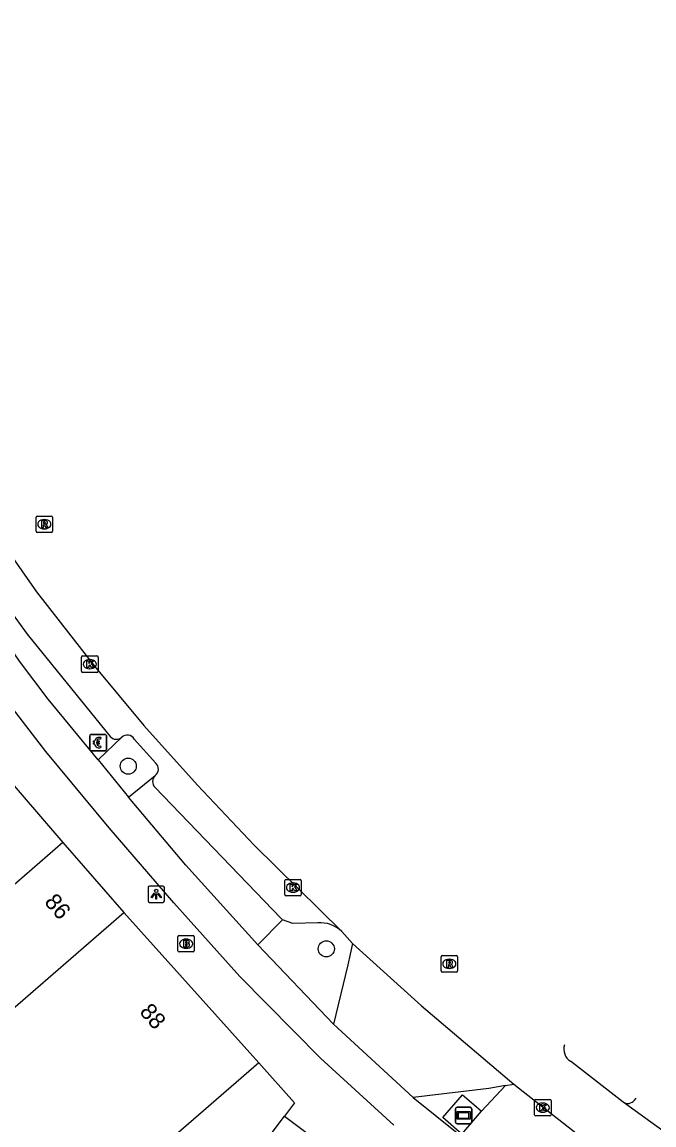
# Model space of a CAD drawing. Extents: x 161845 to 162341, y 381620 to 382158.
# Drawn here: x 162112.3 to 162150.7, y 381850 to 381917 of the extents above; entities that cross this region are included whole.
import ezdxf

# ---------------------------------------------------------------- set-up
doc = ezdxf.new("R2010")
doc.units = 0
for name, color, linetype in [('IMGEO_Berm_groen', 7, 'Continuous'), ('IMGEO_Betaalautomaat', 7, 'Continuous'), ('IMGEO_Boom', 7, 'Continuous'), ('IMGEO_Brandkraan', 7, 'Continuous'), ('IMGEO_Groenvoorziening', 7, 'Continuous'), ('IMGEO_Kolk', 7, 'Continuous'), ('IMGEO_Lichtpunt', 7, 'Continuous'), ('IMGEO_Pand', 7, 'Continuous'), ('IMGEO_Pand_nummerreeks', 7, 'Continuous'), ('IMGEO_Parkeervlak_open', 7, 'Continuous'), ('IMGEO_Reclamebord', 7, 'Continuous'), ('IMGEO_Rijbaan_lokaal_gesloten', 7, 'Continuous'), ('IMGEO_Rijbaan_lokaal_open', 7, 'Continuous'), ('IMGEO_Rioolput', 7, 'Continuous'), ('IMGEO_Voetpad_gesloten', 7, 'Continuous'), ('IMGEO_Voetpad_open', 7, 'Continuous')]:
    doc.layers.add(name, color=color, linetype=linetype)

msp = doc.modelspace()

# ---------------------------------------------------------------- linework, layer by layer
at = {"layer": 'IMGEO_Berm_groen'}
for points in [[(162140.224, 381850.815), (162141.664, 381852.376)], [(162139.024, 381849.428), (162140.224, 381850.815)]]:
    msp.add_lwpolyline(points, dxfattribs=at)
at = {"layer": 'IMGEO_Betaalautomaat'}
for p, q in [((162116.435, 381872.795), (162116.435, 381873.636)), ((162116.435, 381873.636), (162116.435, 381872.795)), ((162116.51, 381873.719), (162117.351, 381873.719)), ((162117.351, 381873.719), (162116.51, 381873.719)), ((162117.434, 381873.645), (162117.434, 381872.804)), ((162117.434, 381872.804), (162117.434, 381873.645)), ((162116.718, 381873.183), (162116.718, 381873.251)), ((162116.839, 381873.251), (162116.839, 381873.183)), ((162117.097, 381873.524), (162117.08, 381873.424)), ((162117.084, 381873.018), (162117.106, 381872.931)), ((162117.36, 381872.72), (162116.519, 381872.72)), ((162116.519, 381872.72), (162117.36, 381872.72))]:
    msp.add_line(p, q, dxfattribs=at)
for points in [[(162116.718, 381873.251), (162116.649, 381873.251), (162116.649, 381873.32), (162116.728, 381873.32)], [(162116.723, 381873.114), (162116.649, 381873.114), (162116.649, 381873.183), (162116.718, 381873.183)], [(162116.85, 381873.32), (162116.997, 381873.32), (162116.997, 381873.251), (162116.839, 381873.251)], [(162116.839, 381873.183), (162116.997, 381873.183), (162116.997, 381873.114), (162116.853, 381873.114)]]:
    msp.add_lwpolyline(points, dxfattribs=at)
for centre, radius, start, end in [((162116.513, 381873.642), 0.0779, 92.4484, 184.28452), ((162116.513, 381873.642), 0.0779, 92.4484, 184.28452), ((162117.357, 381873.642), 0.0779, 2.4484, 94.28452), ((162117.357, 381873.642), 0.0779, 2.4484, 94.28452), ((162116.984, 381873.169), 0.267, 191.80956, 297.03891), ((162117.011, 381873.244), 0.293, 73.01398, 165.01395), ((162117.017, 381873.257), 0.179, 69.32359, 159.56827), ((162117.017, 381873.184), 0.179, 202.76249, 291.86925), ((162116.513, 381872.798), 0.0779, 182.4484, 274.28452), ((162116.513, 381872.798), 0.0779, 182.4484, 274.28452), ((162117.357, 381872.798), 0.0779, 272.4484, 4.28452), ((162117.357, 381872.798), 0.0779, 272.4484, 4.28452)]:
    msp.add_arc(centre, radius, start, end, dxfattribs=at)
at = {"layer": 'IMGEO_Boom'}
for centre in [(162118.764, 381871.787), (162130.79, 381860.685)]:
    msp.add_circle(centre, 0.489, dxfattribs=at)
at = {"layer": 'IMGEO_Brandkraan'}
for p, q in [((162121.775, 381860.573), (162121.775, 381861.425)), ((162121.85, 381861.499), (162122.702, 381861.499)), ((162122.263, 381861.279), (162122.288, 381861.279)), ((162122.776, 381861.425), (162122.776, 381860.573)), ((162122.702, 381860.499), (162121.85, 381860.499)), ((162122.286, 381860.719), (162122.261, 381860.719))]:
    msp.add_line(p, q, dxfattribs=at)
for points in [[(162121.775, 381860.573), (162121.775, 381861.425)], [(162121.85, 381861.499), (162122.702, 381861.499)], [(162122.123, 381861.199), (162122.123, 381860.799), (162122.336, 381860.799)], [(162122.354, 381861.199), (162122.123, 381861.199)], [(162122.302, 381861.118), (162122.248, 381861.118), (162122.248, 381861.042)], [(162122.248, 381861.042), (162122.301, 381861.042)], [(162122.31, 381860.966), (162122.248, 381860.966), (162122.248, 381860.885)], [(162122.248, 381860.885), (162122.31, 381860.885)], [(162122.776, 381861.425), (162122.776, 381860.573)], [(162122.702, 381860.499), (162121.85, 381860.499)]]:
    msp.add_lwpolyline(points, dxfattribs=at)
for centre, radius, start, end in [((162121.852, 381861.423), 0.0765, 91.55205, 178.44795), ((162121.852, 381861.423), 0.0765, 91.55205, 178.44795), ((162122.303, 381861.08), 0.0379, 267.82845, 90.93552), ((162122.311, 381860.925), 0.0404, 269.87594, 90.50774), ((162122.358, 381861.054), 0.145, 59.4692, 91.53667), ((162122.383, 381861.101), 0.0922, 285.51372, 58.15012), ((162122.388, 381860.909), 0.105, 301.31148, 78.98903), ((162122.7, 381861.423), 0.0765, 1.55205, 88.44795), ((162122.7, 381861.423), 0.0765, 1.55205, 88.44795), ((162121.852, 381860.575), 0.0765, 181.55205, 268.44795), ((162121.852, 381860.575), 0.0765, 181.55205, 268.44795), ((162122.342, 381861.05), 0.251, 268.66757, 293.53466), ((162122.7, 381860.575), 0.0765, 271.55205, 358.44795), ((162122.7, 381860.575), 0.0765, 271.55205, 358.44795)]:
    msp.add_arc(centre, radius, start, end, dxfattribs=at)
for centre, major_axis, ratio, start_param, end_param in [((162122.262, 381860.999), (-0.387, 0.002), 0.722429, 4.712389, 7.853982), ((162122.287, 381860.999), (-0.39, 0.002), 0.717154, 1.570796, 4.712389)]:
    msp.add_ellipse(centre, major_axis=major_axis, ratio=ratio, start_param=start_param, end_param=end_param, dxfattribs=at)
at = {"layer": 'IMGEO_Groenvoorziening'}
msp.add_lwpolyline([(162139.024, 381849.428), (162137.867, 381850.429), (162139.067, 381851.816), (162139.757, 381851.219), (162140.224, 381850.815)], dxfattribs=at)
at = {"layer": 'IMGEO_Kolk'}
for p, q in [((162115.929, 381877.559), (162115.929, 381878.411)), ((162116.004, 381878.485), (162116.856, 381878.485)), ((162116.93, 381878.411), (162116.93, 381877.559)), ((162116.44, 381877.705), (162116.415, 381877.705)), ((162116.417, 381878.265), (162116.442, 381878.265)), ((162116.856, 381877.485), (162116.004, 381877.485)), ((162128.345, 381864.908), (162129.197, 381864.908)), ((162128.27, 381863.982), (162128.27, 381864.834)), ((162128.758, 381864.688), (162128.783, 381864.688)), ((162129.271, 381864.834), (162129.271, 381863.982)), ((162129.197, 381863.908), (162128.345, 381863.908)), ((162128.781, 381864.128), (162128.756, 381864.128)), ((162143.513, 381851.534), (162144.365, 381851.534)), ((162143.438, 381850.608), (162143.438, 381851.46)), ((162143.926, 381851.314), (162143.951, 381851.314)), ((162144.439, 381851.46), (162144.439, 381850.608)), ((162144.365, 381850.534), (162143.513, 381850.534)), ((162143.949, 381850.754), (162143.924, 381850.754))]:
    msp.add_line(p, q, dxfattribs=at)
for points in [[(162115.929, 381877.559), (162115.929, 381878.411)], [(162116.004, 381878.485), (162116.856, 381878.485)], [(162116.93, 381878.411), (162116.93, 381877.559)], [(162116.25, 381878.185), (162116.373, 381878.185), (162116.373, 381878.034), (162116.503, 381878.185), (162116.667, 381878.185), (162116.521, 381878.034), (162116.674, 381877.785), (162116.522, 381877.785), (162116.437, 381877.949), (162116.373, 381877.882), (162116.373, 381877.785), (162116.25, 381877.785), (162116.25, 381878.185)], [(162116.856, 381877.485), (162116.004, 381877.485)], [(162128.345, 381864.908), (162129.197, 381864.908)], [(162128.27, 381863.982), (162128.27, 381864.834)], [(162128.591, 381864.608), (162128.714, 381864.608), (162128.714, 381864.457), (162128.844, 381864.608), (162129.008, 381864.608), (162128.862, 381864.457), (162129.015, 381864.208), (162128.863, 381864.208), (162128.778, 381864.372), (162128.714, 381864.305), (162128.714, 381864.208), (162128.591, 381864.208), (162128.591, 381864.608)], [(162129.271, 381864.834), (162129.271, 381863.982)], [(162129.197, 381863.908), (162128.345, 381863.908)], [(162143.513, 381851.534), (162144.365, 381851.534)], [(162143.438, 381850.608), (162143.438, 381851.46)], [(162143.759, 381851.234), (162143.882, 381851.234), (162143.882, 381851.083), (162144.012, 381851.234), (162144.176, 381851.234), (162144.03, 381851.083), (162144.183, 381850.834), (162144.031, 381850.834), (162143.946, 381850.998), (162143.882, 381850.931), (162143.882, 381850.834), (162143.759, 381850.834), (162143.759, 381851.234)], [(162144.439, 381851.46), (162144.439, 381850.608)], [(162144.365, 381850.534), (162143.513, 381850.534)]]:
    msp.add_lwpolyline(points, dxfattribs=at)
for centre, start, end in [((162116.006, 381878.409), 91.55205, 178.44795), ((162116.006, 381878.409), 91.55205, 178.44795), ((162116.854, 381878.409), 1.55205, 88.44795), ((162116.854, 381878.409), 1.55205, 88.44795), ((162116.006, 381877.561), 181.55205, 268.44795), ((162116.006, 381877.561), 181.55205, 268.44795), ((162116.854, 381877.561), 271.55205, 358.44795), ((162116.854, 381877.561), 271.55205, 358.44795), ((162128.347, 381864.832), 91.55205, 178.44795), ((162128.347, 381864.832), 91.55205, 178.44795), ((162129.195, 381864.832), 1.55205, 88.44795), ((162129.195, 381864.832), 1.55205, 88.44795), ((162128.347, 381863.984), 181.55205, 268.44795), ((162128.347, 381863.984), 181.55205, 268.44795), ((162129.195, 381863.984), 271.55205, 358.44795), ((162129.195, 381863.984), 271.55205, 358.44795), ((162143.515, 381851.458), 91.55205, 178.44795), ((162143.515, 381851.458), 91.55205, 178.44795), ((162144.363, 381851.458), 1.55205, 88.44795), ((162144.363, 381851.458), 1.55205, 88.44795), ((162143.515, 381850.61), 181.55205, 268.44795), ((162143.515, 381850.61), 181.55205, 268.44795), ((162144.363, 381850.61), 271.55205, 358.44795), ((162144.363, 381850.61), 271.55205, 358.44795)]:
    msp.add_arc(centre, 0.0765, start, end, dxfattribs=at)
for centre, major_axis, ratio, start_param, end_param in [((162116.416, 381877.985), (-0.387, 0.002), 0.722429, 4.712389, 7.853982), ((162116.441, 381877.985), (-0.39, 0.002), 0.717154, 1.570796, 4.712389), ((162128.757, 381864.408), (-0.387, 0.002), 0.722429, 4.712389, 7.853982), ((162128.782, 381864.408), (-0.39, 0.002), 0.717154, 1.570796, 4.712389), ((162143.925, 381851.034), (-0.387, 0.002), 0.722429, 4.712389, 7.853982), ((162143.95, 381851.034), (-0.39, 0.002), 0.717154, 1.570796, 4.712389)]:
    msp.add_ellipse(centre, major_axis=major_axis, ratio=ratio, start_param=start_param, end_param=end_param, dxfattribs=at)
at = {"layer": 'IMGEO_Lichtpunt'}
for p, q in [((162119.965, 381864.407), (162119.965, 381863.6)), ((162119.965, 381864.407), (162119.965, 381863.6)), ((162120.867, 381864.502), (162120.059, 381864.502)), ((162120.867, 381864.502), (162120.059, 381864.502)), ((162120.961, 381863.6), (162120.961, 381864.407)), ((162120.961, 381863.6), (162120.961, 381864.407)), ((162120.059, 381863.506), (162120.867, 381863.506)), ((162120.059, 381863.506), (162120.867, 381863.506))]:
    msp.add_line(p, q, dxfattribs=at)
for points in [[(162120.339, 381864.071), (162120.378, 381864.043), (162120.19, 381863.781), (162120.152, 381863.808), (162120.339, 381864.071)], [(162120.441, 381864.023), (162120.488, 381864.023), (162120.488, 381863.701), (162120.441, 381863.701), (162120.441, 381864.023)], [(162120.551, 381864.043), (162120.589, 381864.07), (162120.776, 381863.808), (162120.737, 381863.78), (162120.551, 381864.043)]]:
    msp.add_lwpolyline(points, dxfattribs=at)
msp.add_circle((162120.464, 381864.205), 0.0994, dxfattribs=at)
for centre, start, end in [((162120.059, 381864.407), 90, 180), ((162120.059, 381864.407), 90, 180), ((162120.867, 381864.407), 0, 90), ((162120.867, 381864.407), 0, 90), ((162120.059, 381863.6), 180, 270), ((162120.059, 381863.6), 180, 270), ((162120.867, 381863.6), 270, 0), ((162120.867, 381863.6), 270, 360)]:
    msp.add_arc(centre, 0.0946, start, end, dxfattribs=at)
at = {"layer": 'IMGEO_Pand'}
for points in [[(162110.94, 381871.605), (162114.795, 381867.156)], [(162114.795, 381867.156), (162108.715, 381861.887), (162107.979, 381862.737), (162100.673, 381856.414), (162099.355, 381857.936), (162089.659, 381849.709)], [(162114.795, 381867.156), (162118.49, 381862.892)], [(162098.619, 381845.654), (162109.895, 381855.443), (162118.49, 381862.892)], [(162118.49, 381862.892), (162126.698, 381853.761)], [(162126.698, 381853.761), (162120.737, 381848.595), (162121.682, 381847.505), (162114.735, 381838.122)]]:
    msp.add_lwpolyline(points, dxfattribs=at)
at = {"layer": 'IMGEO_Parkeervlak_open'}
for points in [[(162120.441, 381871.976), (162119.124, 381873.432)], [(162130.268, 381862.266), (162128.757, 381862.224), (162128.126, 381862.446)]]:
    msp.add_lwpolyline(points, dxfattribs=at)
for centre, radius, start, end in [((162118.701, 381873.196), 0.484, 29.19225, 132.47826), ((162120.086, 381871.614), 0.506, 308.12397, 45.54977), ((162130.415, 381860.376), 1.896, 46.2334, 94.43904)]:
    msp.add_arc(centre, radius, start, end, dxfattribs=at)
at = {"layer": 'IMGEO_Reclamebord'}
for p, q in [((162138.632, 381850.161), (162138.632, 381850.961)), ((162138.632, 381850.961), (162138.632, 381850.161)), ((162138.732, 381851.061), (162139.522, 381851.061)), ((162139.522, 381851.061), (162138.732, 381851.061)), ((162139.622, 381850.961), (162139.622, 381850.161)), ((162139.622, 381850.161), (162139.622, 381850.961)), ((162139.522, 381850.061), (162138.732, 381850.061)), ((162138.732, 381850.061), (162139.522, 381850.061))]:
    msp.add_line(p, q, dxfattribs=at)
for points in [[(162138.733, 381850.793), (162139.521, 381850.793), (162139.521, 381850.329), (162138.733, 381850.329), (162138.733, 381850.793)], [(162138.798, 381850.728), (162138.798, 381850.394), (162139.456, 381850.394), (162139.456, 381850.728), (162138.798, 381850.728)]]:
    msp.add_lwpolyline(points, dxfattribs=at)
for centre, start, end in [((162138.732, 381850.961), 90, 180), ((162138.732, 381850.961), 90, 180), ((162139.522, 381850.961), 0, 90), ((162139.522, 381850.961), 360, 90), ((162138.732, 381850.161), 180, 270), ((162138.732, 381850.161), 180, 270), ((162139.522, 381850.161), 270, 0), ((162139.522, 381850.161), 270, 0)]:
    msp.add_arc(centre, 0.1, start, end, dxfattribs=at)
at = {"layer": 'IMGEO_Rijbaan_lokaal_gesloten'}
for points in [[(162092.687, 381916.789), (162101.169, 381901.585), (162104.943, 381895.096), (162107.401, 381891.02), (162110.364, 381886.414), (162113.19, 381882.377), (162116.706, 381877.858), (162119.709, 381874.255), (162122.966, 381870.633), (162126.414, 381866.991), (162131.726, 381861.745)], [(162131.726, 381861.745), (162132.386, 381861.014)], [(162148.821, 381851.365), (162145.621, 381853.854)], [(162142.172, 381852.464), (162147.466, 381848.311)], [(162152.909, 381848.404), (162148.821, 381851.365)]]:
    msp.add_lwpolyline(points, dxfattribs=at)
msp.add_arc((162146.054, 381854.573), 0.839, 161.29895, 238.94639, dxfattribs=at)
at = {"layer": 'IMGEO_Rijbaan_lokaal_open'}
for points in [[(162132.386, 381861.014), (162132.098, 381859.71), (162131.221, 381856.117)], [(162132.386, 381861.014), (162136.567, 381857.218), (162142.172, 381852.464)], [(162131.221, 381856.117), (162136.067, 381851.659)], [(162141.664, 381852.376), (162140.664, 381852.202), (162136.067, 381851.659)], [(162141.664, 381852.376), (162142.172, 381852.464)], [(162123.069, 381843.607), (162128.26, 381850.52)], [(162128.26, 381850.52), (162131.013, 381848.456)]]:
    msp.add_lwpolyline(points, dxfattribs=at)
at = {"layer": 'IMGEO_Rioolput'}
for p, q in [((162113.164, 381886.063), (162113.164, 381886.915)), ((162113.239, 381886.989), (162114.091, 381886.989)), ((162113.652, 381886.769), (162113.677, 381886.769)), ((162114.165, 381886.915), (162114.165, 381886.063)), ((162114.091, 381885.989), (162113.239, 381885.989)), ((162113.675, 381886.209), (162113.65, 381886.209)), ((162137.761, 381859.35), (162137.761, 381860.202)), ((162137.836, 381860.276), (162138.688, 381860.276)), ((162138.762, 381860.202), (162138.762, 381859.35)), ((162138.249, 381860.056), (162138.274, 381860.056)), ((162138.688, 381859.276), (162137.836, 381859.276)), ((162138.272, 381859.496), (162138.247, 381859.496))]:
    msp.add_line(p, q, dxfattribs=at)
for points in [[(162113.164, 381886.063), (162113.164, 381886.915)], [(162113.239, 381886.989), (162114.091, 381886.989)], [(162113.753, 381886.687), (162113.501, 381886.689), (162113.501, 381886.289)], [(162113.501, 381886.289), (162113.625, 381886.289), (162113.625, 381886.451), (162113.636, 381886.451)], [(162113.679, 381886.608), (162113.625, 381886.608), (162113.625, 381886.527)], [(162113.625, 381886.527), (162113.677, 381886.527)], [(162113.683, 381886.422), (162113.754, 381886.289), (162113.894, 381886.289), (162113.829, 381886.415)], [(162114.165, 381886.915), (162114.165, 381886.063)], [(162114.091, 381885.989), (162113.239, 381885.989)], [(162137.761, 381859.35), (162137.761, 381860.202)], [(162137.836, 381860.276), (162138.688, 381860.276)], [(162138.762, 381860.202), (162138.762, 381859.35)], [(162138.35, 381859.974), (162138.098, 381859.976), (162138.098, 381859.576)], [(162138.098, 381859.576), (162138.222, 381859.576), (162138.222, 381859.738), (162138.233, 381859.738)], [(162138.276, 381859.895), (162138.222, 381859.895), (162138.222, 381859.814)], [(162138.222, 381859.814), (162138.274, 381859.814)], [(162138.28, 381859.709), (162138.351, 381859.576), (162138.491, 381859.576), (162138.426, 381859.702)], [(162138.688, 381859.276), (162137.836, 381859.276)]]:
    msp.add_lwpolyline(points, dxfattribs=at)
for centre, radius, start, end in [((162113.241, 381886.913), 0.0765, 91.55205, 178.44795), ((162113.241, 381886.913), 0.0765, 91.55205, 178.44795), ((162113.635, 381886.398), 0.0533, 26.02933, 88.69889), ((162113.661, 381886.716), 0.19, 274.7715, 282.96867), ((162113.685, 381886.512), 0.0964, 77.00612, 93.18647), ((162113.699, 381886.569), 0.0378, 276.66336, 79.67722), ((162113.752, 381886.577), 0.109, 350.36119, 89.41601), ((162113.75, 381886.577), 0.112, 277.58423, 350.98172), ((162113.734, 381886.362), 0.108, 29.51342, 73.79051), ((162114.089, 381886.913), 0.0765, 1.55205, 88.44795), ((162114.089, 381886.913), 0.0765, 1.55205, 88.44795), ((162113.241, 381886.065), 0.0765, 181.55205, 268.44795), ((162113.241, 381886.065), 0.0765, 181.55205, 268.44795), ((162114.089, 381886.065), 0.0765, 271.55205, 358.44795), ((162114.089, 381886.065), 0.0765, 271.55205, 358.44795), ((162137.838, 381860.2), 0.0765, 91.55205, 178.44795), ((162137.838, 381860.2), 0.0765, 91.55205, 178.44795), ((162138.686, 381860.2), 0.0765, 1.55205, 88.44795), ((162138.686, 381860.2), 0.0765, 1.55205, 88.44795), ((162138.232, 381859.685), 0.0533, 26.02933, 88.69889), ((162138.258, 381860.003), 0.19, 274.7715, 282.96867), ((162138.282, 381859.799), 0.0964, 77.00612, 93.18647), ((162138.296, 381859.856), 0.0378, 276.66336, 79.67722), ((162138.349, 381859.864), 0.109, 350.36119, 89.41601), ((162138.347, 381859.864), 0.112, 277.58423, 350.98172), ((162138.331, 381859.649), 0.108, 29.51342, 73.79051), ((162137.838, 381859.352), 0.0765, 181.55205, 268.44795), ((162137.838, 381859.352), 0.0765, 181.55205, 268.44795), ((162138.686, 381859.352), 0.0765, 271.55205, 358.44795), ((162138.686, 381859.352), 0.0765, 271.55205, 358.44795)]:
    msp.add_arc(centre, radius, start, end, dxfattribs=at)
for centre, major_axis, ratio, start_param, end_param in [((162113.651, 381886.489), (-0.387, 0.002), 0.722429, 4.712389, 7.853982), ((162113.676, 381886.489), (-0.39, 0.002), 0.717154, 1.570796, 4.712389), ((162138.248, 381859.776), (-0.387, 0.002), 0.722429, 4.712389, 7.853982), ((162138.273, 381859.776), (-0.39, 0.002), 0.717154, 1.570796, 4.712389)]:
    msp.add_ellipse(centre, major_axis=major_axis, ratio=ratio, start_param=start_param, end_param=end_param, dxfattribs=at)
at = {"layer": 'IMGEO_Voetpad_gesloten'}
for points in [[(162134.882, 381849.978), (162130.429, 381854.037), (162125.545, 381859.011), (162121.54, 381863.477), (162117.602, 381868.047), (162113.764, 381872.679), (162110.7, 381876.627), (162107.813, 381880.741), (162103.406, 381887.421), (162102.392, 381889.138), (162058.476, 381968.271)], [(162116.928, 381872.165), (162113.906, 381875.863), (162112.159, 381878.177), (162105.585, 381887.798)], [(162116.928, 381872.165), (162118.784, 381869.911)], [(162126.623, 381860.928), (162122.269, 381865.766), (162118.784, 381869.911)], [(162126.623, 381860.928), (162131.221, 381856.117)], [(162136.067, 381851.659), (162138.949, 381849.346)]]:
    msp.add_lwpolyline(points, dxfattribs=at)
at = {"layer": 'IMGEO_Voetpad_open'}
for points in [[(162106.682, 381888.476), (162108.547, 381885.543), (162110.249, 381883.047), (162112.617, 381879.817), (162117.669, 381873.59)], [(162118.374, 381873.553), (162116.928, 381872.165)], [(162118.784, 381869.911), (162120.399, 381871.216)], [(162120.383, 381870.501), (162128.045, 381862.528), (162128.126, 381862.446)], [(162128.126, 381862.446), (162126.623, 381860.928)], [(162126.698, 381853.761), (162128.867, 381851.329), (162128.26, 381850.52)], [(162149.5, 381851.48), (162149.598, 381851.604), (162149.598, 381851.604)]]:
    msp.add_lwpolyline(points, dxfattribs=at)
for centre, radius, start, end in [((162118.039, 381873.912), 0.491, 221.03579, 312.9557), ((162120.745, 381870.851), 0.503, 133.46594, 223.9702), ((162149.094, 381851.815), 0.526, 238.73764, 320.48791)]:
    msp.add_arc(centre, radius, start, end, dxfattribs=at)

# ---------------------------------------------------------------- texts
at = {"layer": 'IMGEO_Pand_nummerreeks'}
for s, rotation, p in [('86', 310.9108, (162113.623, 381863.501)), ('88', 310.91246, (162119.403, 381856.83))]:
    msp.add_text(s, height=1, rotation=rotation, dxfattribs=at).set_placement(p)

doc.saveas('drawing.dxf')
